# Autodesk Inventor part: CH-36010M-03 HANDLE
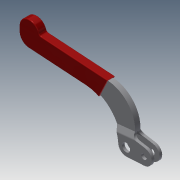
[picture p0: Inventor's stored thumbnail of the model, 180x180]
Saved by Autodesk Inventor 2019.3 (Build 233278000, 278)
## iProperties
Created: 2012-09
Part Number: CH-36010M-03 HANDLE
Material: Ogólny
Document SubType Name: Modeling
Designer: CADENGINEERING4
Density: 1 g/cm^3
Appearance: Domyślna
Author: CADENGINEERING4
Revision Number: ÈÎºÎ
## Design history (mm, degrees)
feature "Ô²½Ç2"
node "Bryła1"
